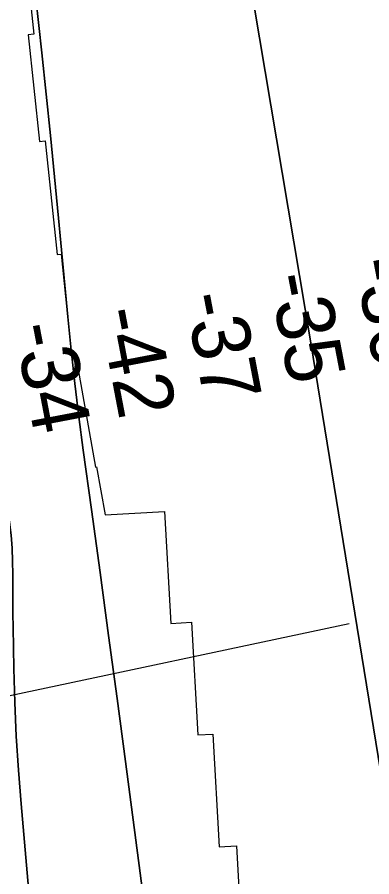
# Model space of a CAD drawing. Extents: x 3263578 to 3301413, y 764927 to 798602.
# Drawn here: x 3276097 to 3276507, y 792245 to 793237 of the extents above; entities that cross this region are included whole.
import ezdxf

# ---------------------------------------------------------------- set-up
doc = ezdxf.new("R2010")
doc.units = 0
for name, color, linetype in [('V-RIVR-RANG', 7, 'Continuous'), ('V-RRAP-RVMT', 7, 'Continuous'), ('V-TOPO-DPTH', 7, 'Continuous'), ('V-TOPO-MINR', 7, 'Continuous')]:
    doc.layers.add(name, color=color, linetype=linetype)

msp = doc.modelspace()

# ---------------------------------------------------------------- linework, layer by layer
at = {"layer": 'V-RIVR-RANG'}
msp.add_line((3275668.76, 792364.9), (3276480.42, 792537.23), dxfattribs=at)
at = {"layer": 'V-RRAP-RVMT'}
for points in [[(3276101.98, 793356.84), (3276116.6, 793217.53), (3276110.11, 793216.83), (3276123.02, 793093.6), (3276129.57, 793094.3), (3276143.39, 792963.04), (3276147.96, 792963.49), (3276160.13, 792847), (3276164.74, 792847.8), (3276187.64, 792717.8), (3276188.98, 792718.03), (3276198.75, 792662.58), (3276267.24, 792666.6)], [(3276267.24, 792666.6), (3276274.68, 792537.22), (3276298.41, 792538.57), (3276305.94, 792408.68), (3276322.98, 792409.51), (3276330.56, 792279.44), (3276350.63, 792280.61), (3276358.29, 792140.86), (3276354.91, 792140.71), (3276361.31, 792022.46), (3276383.18, 792023.54), (3276389.99, 791893.13), (3276403.81, 791893.89), (3276411.76, 791748.26), (3276441.88, 791749.86), (3276449.37, 791604.37), (3276466.05, 791605.25), (3276473.51, 791459.54), (3276485.65, 791460.18), (3276493.76, 791314.12)]]:
    msp.add_lwpolyline(points, dxfattribs=at)
at = {"layer": 'V-TOPO-DPTH'}
for points in [[(3276686.19, 791360.51), (3276669.75, 791449.59), (3276649.15, 791562.27), (3276643.25, 791595.06), (3276637.48, 791627.87), (3276631.91, 791660.72), (3276626.46, 791693.58), (3276436.34, 792860.97), (3276317.88, 793565.76), (3276311.89, 793601.35), (3276305.9, 793636.93), (3276299.9, 793672.51), (3276293.9, 793708.09), (3276288.02, 793743.69), (3276282.31, 793779.32), (3276276.86, 793814.99), (3276271.59, 793850.68), (3276247.8, 794016.15), (3276524.26, 794016.17)], [(3276247.8, 794016.15), (3276271.59, 793850.68), (3276276.86, 793814.99), (3276282.31, 793779.32), (3276288.02, 793743.69), (3276293.9, 793708.09), (3276299.9, 793672.51), (3276305.9, 793636.93), (3276311.89, 793601.35), (3276317.88, 793565.76), (3276436.34, 792860.97), (3276626.46, 791693.58), (3276631.91, 791660.72), (3276637.48, 791627.87), (3276643.25, 791595.06), (3276649.15, 791562.27), (3276669.75, 791449.59), (3276686.19, 791360.51)], [(3276135.01, 791948.53), (3276101.79, 792328.94), (3276098.78, 792367.95), (3276096.31, 792406.98), (3276094.63, 792446.05), (3276093.49, 792485.16), (3276092.57, 792533.02), (3276092.35, 792548.21), (3276092.21, 792563.41), (3276092.2, 792578.61), (3276092.28, 792593.8), (3276092.11, 792608.98), (3276091.5, 792624.13), (3276090.25, 792639.24), (3276088.56, 792654.33), (3276079.57, 792721.89), (3276074.83, 792757.83), (3276070.13, 792793.79), (3276065.5, 792829.75), (3276060.91, 792865.71), (3276034.21, 793076.97), (3276026.46, 793147.2), (3276020.21, 793217.55), (3276016.19, 793288.05)], [(3276135.01, 791948.53), (3276101.79, 792328.94), (3276098.78, 792367.95), (3276096.31, 792406.98), (3276094.63, 792446.05), (3276093.49, 792485.16), (3276092.57, 792533.02), (3276092.35, 792548.21), (3276092.21, 792563.41), (3276092.2, 792578.61), (3276092.28, 792593.8), (3276092.11, 792608.98), (3276091.5, 792624.13), (3276090.25, 792639.24), (3276088.56, 792654.33), (3276079.57, 792721.89), (3276074.83, 792757.83), (3276070.13, 792793.79), (3276065.5, 792829.75), (3276060.91, 792865.71), (3276034.21, 793076.97), (3276026.46, 793147.2), (3276020.21, 793217.55), (3276016.19, 793288.05)], [(3276115.29, 793291.11), (3276125.93, 793195.83), (3276135.77, 793100.46), (3276145.08, 793005.03), (3276155.71, 792891.16), (3276159.56, 792852.66), (3276163.75, 792814.19), (3276168.46, 792775.78), (3276173.51, 792737.41), (3276183.01, 792668.76), (3276193, 792596.08), (3276202.9, 792523.39), (3276212.66, 792450.68), (3276222.33, 792377.96), (3276251.34, 792158.16)], [(3276251.34, 792158.16), (3276222.33, 792377.96), (3276212.66, 792450.68), (3276202.9, 792523.39), (3276193, 792596.08), (3276183.01, 792668.76), (3276173.51, 792737.41), (3276168.46, 792775.78), (3276163.75, 792814.19), (3276159.56, 792852.66), (3276155.71, 792891.16), (3276145.08, 793005.03), (3276135.77, 793100.46), (3276125.93, 793195.83), (3276115.29, 793291.11)]]:
    msp.add_lwpolyline(points, dxfattribs=at)
at = {"layer": 'V-TOPO-MINR'}
for points in [[(3276686.19, 791360.51), (3276669.75, 791449.59), (3276649.15, 791562.27), (3276643.25, 791595.06), (3276637.48, 791627.87), (3276631.91, 791660.72), (3276626.46, 791693.58), (3276436.34, 792860.97), (3276317.88, 793565.76), (3276311.89, 793601.35), (3276305.9, 793636.93), (3276299.9, 793672.51), (3276293.9, 793708.09), (3276288.02, 793743.69), (3276282.31, 793779.32), (3276276.86, 793814.99), (3276271.59, 793850.68), (3276247.8, 794016.15)], [(3276016.19, 793288.05), (3276020.21, 793217.55), (3276026.46, 793147.2), (3276034.21, 793076.97), (3276060.91, 792865.71), (3276065.5, 792829.75), (3276070.13, 792793.79), (3276074.83, 792757.83), (3276079.57, 792721.89), (3276088.56, 792654.33), (3276090.25, 792639.24), (3276091.5, 792624.13), (3276092.11, 792608.98), (3276092.28, 792593.8), (3276092.2, 792578.61), (3276092.21, 792563.41), (3276092.35, 792548.21), (3276092.57, 792533.02), (3276093.49, 792485.16), (3276094.63, 792446.05), (3276096.31, 792406.98), (3276098.78, 792367.95), (3276101.79, 792328.94), (3276135.01, 791948.53)], [(3276115.29, 793291.11), (3276125.93, 793195.83), (3276135.77, 793100.46), (3276145.08, 793005.03), (3276155.71, 792891.16), (3276159.56, 792852.66), (3276163.75, 792814.19), (3276168.46, 792775.78), (3276173.51, 792737.41), (3276183.01, 792668.76), (3276193, 792596.08), (3276202.9, 792523.39), (3276212.66, 792450.68), (3276222.33, 792377.96), (3276251.34, 792158.16)]]:
    msp.add_lwpolyline(points, dxfattribs=at)

# ---------------------------------------------------------------- texts
at = {"layer": 'V-RIVR-RANG'}
for s, p in [('-30', (3276486, 792955.35)), ('-35', (3276387.59, 792937.58)), ('-37', (3276290.06, 792915.17)), ('-42', (3276191.55, 792897.91)), ('-34', (3276093.14, 792880.15))]:
    msp.add_text(s, height=67, rotation=280.826, dxfattribs=at).set_placement(p)

doc.saveas('drawing.dxf')
